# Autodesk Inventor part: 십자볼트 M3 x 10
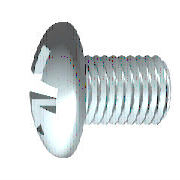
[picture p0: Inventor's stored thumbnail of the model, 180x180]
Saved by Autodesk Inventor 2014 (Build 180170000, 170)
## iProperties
IsCustomPart: 0
Created: 2012-02
Part Number: 십자볼트 M3 x 10
Material: 스테인리스강
Description: 십자 오목 머리 나사
Document SubType Name: Modeling
Standard: KS B 1023
Designer: mduedu
Standards Organization: KS
Language: ko-KR
Size Designation: A  M 3 x 10 - H
Categories: <MemberInstance><Categories><Category DisplayName="조임쇠" InternalName="e4da775c-781d-43d5-af7c-5136215cf5a6" Mnemonic="FSTN"><Category DisplayName="볼트" InternalN
Density: 1 g/cm^3
Appearance: 반광택
Author: mduedu
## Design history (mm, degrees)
body "Solid1"
workplane "Work Plane3"
sketch "스케치2"
  geometry: L1 (-3.72, 0)-(3.72, 0) reference; L2 (0, -3.72)-(0, 3.72) reference; L3 (0, 1.5)-(0, 0); L4 (0, 0)-(1.5, 0); L5 (0, 0)-(1.879, 1.879); L6 (0.253, 1.479)-(0.261, 0.456); L7 (1.479, 0.253)-(0.456, 0.261); L8 (0.253, -1.479)-(0.261, -0.456); L9 (1.479, -0.253)-(0.456, -0.261); L10 (-0.253, 1.479)-(-0.261, 0.456); L11 (-1.479, 0.253)-(-0.456, 0.261); L12 (-1.479, -0.253)-(-0.456, -0.261); L13 (-0.253, -1.479)-(-0.261, -0.456); A1 r 0.45 centre (0, 0) between (0.45, 0) and (0, 0.45); A2 r 1.5 centre (0, 0) between (1.5, 0) and (1.479, 0.253); A3 r 1.5 centre (0, 0) between (0.253, 1.479) and (0, 1.5); A4 r 1.5 centre (0, 0) between (1.479, 0.253) and (0.253, 1.479); A5 r 1.5 centre (0, 0) between (0, -1.5) and (0.253, -1.479); A6 r 1.5 centre (0, 0) between (0.253, -1.479) and (1.479, -0.253); A7 r 1.5 centre (0, 0) between (1.479, -0.253) and (1.5, 0); A8 r 1.5 centre (0, 0) between (-1.479, 0.253) and (-1.5, 0); A9 r 1.5 centre (0, 0) between (-0.253, 1.479) and (-1.479, 0.253); A10 r 1.5 centre (0, 0) between (0, 1.5) and (-0.253, 1.479); A11 r 1.5 centre (0, 0) between (-1.5, 0) and (-1.479, -0.253); A12 r 1.5 centre (0, 0) between (-1.479, -0.253) and (-0.253, -1.479); A13 r 1.5 centre (0, 0) between (-0.253, -1.479) and (0, -1.5); A14 r 0.525 centre (0, 0) between (0.525, 0) and (0, 0.525); A15 r 0.197 centre (0.457, 0.457) between (0.261, 0.456) and (0.456, 0.261); A16 r 0.197 centre (0.457, -0.457) between (0.456, -0.261) and (0.261, -0.456); A17 r 0.197 centre (-0.457, 0.457) between (-0.456, 0.261) and (-0.261, 0.456); A18 r 0.197 centre (-0.457, -0.457) between (-0.261, -0.456) and (-0.456, -0.261); 1 further point
  constraints: 38 point on circle, 22 end point, 19 symmetric about line, 18 centre point, 4 coincident, 3 collinear, 3 point on line, 3 tangent, 1 perpendicular, 21 other
  dimensions: "d4" = 45 deg angle of L5 L4; "d5" = 0.9 diameter of A1 (= 0.3 x SDM); "d6" = 3 diameter of A4 (= SDM); "d7" = 0.2525 distance from line of L6.start L3 (= 0.5 x SBR); "d14" = 1.05 diameter of A14 (= 0.35 x SDM)
extrude "슬롯" join sketch "스케치2" taper "d15" = 5 deg; stored distance "d54" = 10
revolve "절단부" stored, may be unused: angle "d56" = 90 deg
revolve "본체" stored, may be unused: angle "d18" = 90 deg
workplane "Work Plane1"
sketch "스케치1"
  geometry: L1 (10, 0)-(10, 1.5); L2 (10, 1.5)-(1, 1.5); L3 (3.962, 5.08)-(3.962, 5.08); L4 (-2.4, 0)-(-2.4, 2.59); L5 (-2.2, 1.4)-(-1.036, 0.82); L6 (-1.036, 0.82)-(-0.6, 0); L7 (-0.6, 0)-(10, 0); L8 (-5.105, 0)-(12.517, 0) reference; L9 (0, -1.016)-(0, 6.096) reference; L10 (-2.2, 1.4)-(-2.4, 1.5); L11 (-1.636, 2.657)-(-2.4, 2.59); L12 (-1.636, 2.657)-(0, 2.8); L13 (0, 2.8)-(0, 1.347); L14 (0, 1.347)-(0.693, 1.347); L15 (0.693, 1.347)-(1, 1.5); L16 (1, 1.5)-(0, 1.5); A1 r 5 centre (2.6, 0) between (-1.636, 2.657) and (-2.4, 0)
  constraints: 28 end point, 5 point on line, 4 collinear, 4 point on circle, 3 parallel, 2 perpendicular, 1 centre point, 1 horizontal, 1 tangent
  dimensions: "d1" = 3 diameter of L2 L7 (= GD); "d2" = 1.8 distance from line of L6.end L4 (= STI); "d11" = 3 diameter of L10.end L7 (= SDM); "d12" = 62 deg angle of L6 L7; "d13" = 26.5 deg angle of L5 L7; "d17" = 5.6 diameter of L12.end L7 (= KOD); "d19" = 5 deg angle of L12 L7 (= KEWI); "d20" = 2.4 distance between parallel lines of L4 L13 (= KOH); "d21" = 5 radius of A1 (= KR); "d23" = 2.6935 diameter of L14 L7 (= BDM); "d24" = 9 distance of L1.end L2.end (= GEL); "d25" = 0.30673 horizontal distance of L14.end L2.end (= GAL); "d28" = 10 distance between parallel lines of L1 L13 (= NLG)
fillet "모깎기1" dims "d29" = 1.2 (= RR)
fillet "모깎기2" dims "d16" = 0.101 (= 0.2 x SBR)
feature "스레드" dims "d8" = 9 (= GEL), "d9" = 0
chamfer "모따기1" distance "d26" = 0.30673 (= -0.5 x SPD + 0.5 x GD); stored, may be unused: second distance "d27" = 0.30683 (computed from GUL), angle "d78" = 45 deg
other parameters: "GD" = 3 (= NND) [user parameter; used in 2 equation terms], "NLG" = 10 [user parameter; used in 1 equation term], "GEL" = 9 [user parameter; used in 2 equation terms], "KOD" = 5.6 [user parameter; used in 1 equation term], "KOH" = 2.4 [user parameter; used in 2 equation terms], "SDM" = 3 [user parameter; used in 4 equation terms], "STI" = 1.8 [user parameter; used in 1 equation term], "SBR" = 0.505 [user parameter; used in 2 equation terms], "GAL" = 0.30673 (= 0.61345 x PTC) [user parameter; used in 1 equation term], "SPD" = 2.38655 (= NND - 1.2269 x PTC) [user parameter; used in 1 equation term], "KEWI" = 5 deg [user parameter; used in 1 equation term], "d3" = -2.4 (= -KOH), "d10" = 0, "KR" = 5 [user parameter; used in 1 equation term], "BDM" = 2.6935 [user parameter; used in 1 equation term], "GUL" = 0.30673 (= 0.61345 x PTC) [user parameter; used in 1 equation term], "RR" = 1.2 [user parameter; used in 1 equation term], "d79" = 0, "d80" = 0, "PTC" = 0.5 [user parameter; used in 5 equation terms], "THREADDIA" = 3 [user parameter; used in 1 equation term], "TOA" = 30 deg [user parameter], "NND" = 3 [user parameter; used in 2 equation terms], "GD1" = 2.38655 (= THREADDIA - 1.2269 x PTC) [user parameter]
